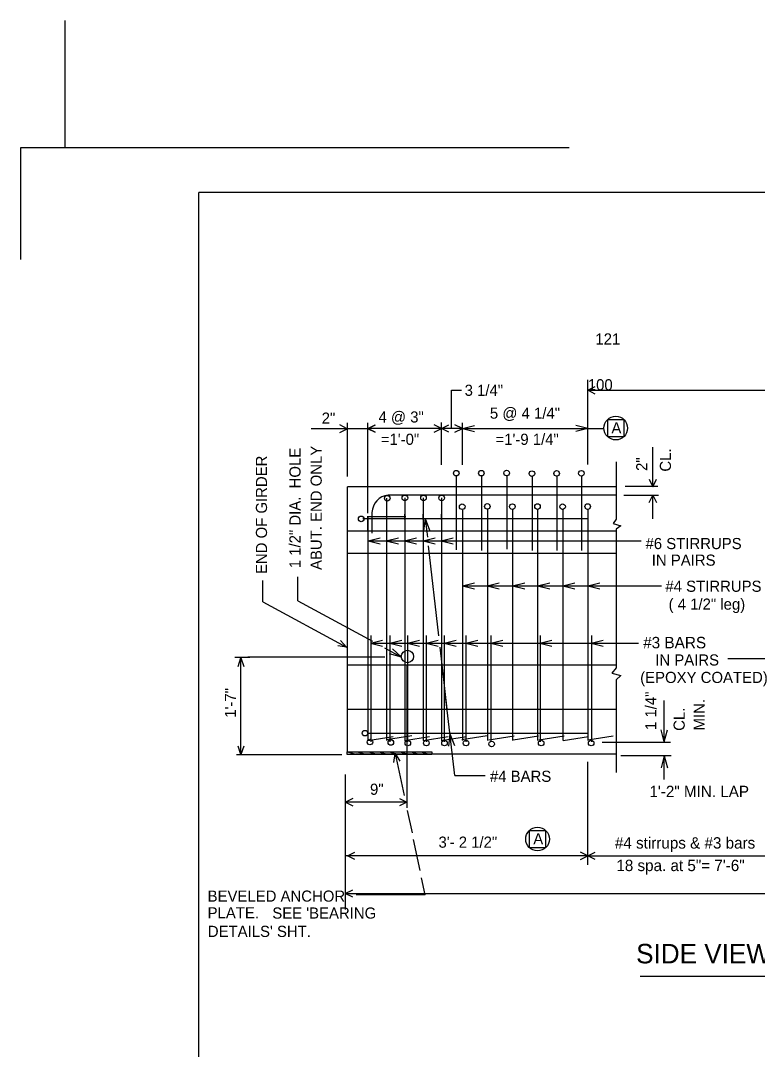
# Model space of a CAD drawing. Extents: x 1005 to 1123, y 2008 to 2074.
# Drawn here: x 1008.66 to 1030.68, y 2043.4 to 2074.18 of the extents above; entities that cross this region are included whole.
import ezdxf

# ---------------------------------------------------------------- set-up
doc = ezdxf.new("R2010")
doc.units = 0
for name, color, linetype in [('Level 1', 7, 'Continuous'), ('Level 2', 7, 'Continuous'), ('Level 5', 7, 'Continuous'), ('Level 6', 7, 'Continuous'), ('Level 60', 7, 'Continuous')]:
    doc.layers.add(name, color=color, linetype=linetype)

msp = doc.modelspace()

# ---------------------------------------------------------------- linework, layer by layer
at = {"layer": 'Level 1'}
for p, q in [((1025.057, 2070.374), (1008.656, 2070.374)), ((1008.656, 2070.374), (1008.656, 2067.034)), ((1013.989, 2013.041), (1013.989, 2069.04)), ((1097.657, 2069.04), (1013.989, 2069.04))]:
    msp.add_line(p, q, dxfattribs=at)
at = {"layer": 'Level 2'}
for p, q in [((1009.989, 2070.374), (1009.989, 2074.178)), ((1025.614, 2060.904), (1025.614, 2063.43)), ((1021.537, 2061.975), (1021.537, 2063.122)), ((1021.537, 2063.122), (1021.839, 2063.122)), ((1025.617, 2063.119), (1052.076, 2063.119)), ((1018.426, 2060.537), (1018.426, 2062.142)), ((1019.039, 2059.444), (1019.039, 2062.142)), ((1021.239, 2060.885), (1021.239, 2062.153)), ((1021.864, 2060.891), (1021.864, 2062.142)), ((1026.698, 2062.239), (1026.198, 2062.239)), ((1026.198, 2062.239), (1026.198, 2061.739)), ((1026.698, 2061.739), (1026.698, 2062.239)), ((1019.039, 2061.97), (1017.341, 2061.97)), ((1021.864, 2061.975), (1019.039, 2061.975)), ((1021.864, 2061.975), (1022.224, 2062.065)), ((1021.864, 2061.975), (1026.089, 2061.975)), ((1021.864, 2061.975), (1022.224, 2061.885)), ((1025.614, 2061.975), (1025.254, 2062.065)), ((1025.614, 2061.975), (1025.254, 2062.065)), ((1025.614, 2061.975), (1025.254, 2061.885)), ((1025.614, 2061.975), (1025.254, 2061.885)), ((1026.198, 2061.739), (1026.698, 2061.739)), ((1026.202, 2061.739), (1026.202, 2061.739)), ((1027.559, 2060.236), (1027.559, 2061.418)), ((1026.466, 2060.978), (1026.466, 2059.266)), ((1021.679, 2060.562), (1021.679, 2058.351)), ((1023.19, 2060.581), (1023.19, 2058.37)), ((1022.434, 2060.543), (1022.434, 2058.332)), ((1023.946, 2060.543), (1023.946, 2058.332)), ((1024.683, 2060.543), (1024.683, 2058.332)), ((1025.42, 2060.543), (1025.42, 2058.332)), ((1026.735, 2060.247), (1027.702, 2060.247)), ((1026.466, 2060.236), (1018.426, 2060.236)), ((1018.426, 2052.307), (1018.426, 2060.236)), ((1026.466, 2059.986), (1019.644, 2059.986)), ((1026.689, 2059.986), (1027.725, 2059.986)), ((1027.559, 2059.277), (1027.559, 2059.986)), ((1019.599, 2059.895), (1019.599, 2053.827)), ((1020.14, 2059.905), (1020.14, 2052.647)), ((1020.696, 2059.905), (1020.696, 2052.647)), ((1021.239, 2059.905), (1021.239, 2052.647)), ((1019.039, 2058.922), (1019.039, 2059.35)), ((1019.039, 2059.347), (1020.169, 2059.347)), ((1019.039, 2059.347), (1019.039, 2052.647)), ((1019.158, 2059.468), (1019.158, 2058.847)), ((1020.14, 2059.25), (1020.14, 2059.411)), ((1020.696, 2059.25), (1020.696, 2059.411)), ((1021.239, 2059.25), (1021.239, 2059.411)), ((1021.864, 2059.541), (1021.864, 2052.647)), ((1022.614, 2059.56), (1022.614, 2052.647)), ((1023.364, 2059.56), (1023.364, 2052.647)), ((1024.114, 2059.57), (1024.114, 2052.647)), ((1024.864, 2059.551), (1024.864, 2052.647)), ((1025.614, 2059.56), (1025.614, 2052.647)), ((1018.885, 2059.28), (1025.614, 2059.28)), ((1020.754, 2059.28), (1020.705, 2058.912)), ((1020.754, 2059.28), (1020.884, 2058.932)), ((1020.754, 2059.28), (1020.817, 2058.725)), ((1026.466, 2059.266), (1026.367, 2059.134)), ((1026.367, 2059.134), (1026.598, 2059.068)), ((1026.598, 2059.068), (1026.466, 2058.97)), ((1026.466, 2058.903), (1018.426, 2058.903)), ((1019.048, 2058.616), (1019.408, 2058.706)), ((1019.59, 2058.616), (1019.95, 2058.706)), ((1020.129, 2058.616), (1020.489, 2058.706)), ((1020.688, 2058.616), (1021.048, 2058.706)), ((1021.229, 2058.616), (1021.589, 2058.706)), ((1026.466, 2058.97), (1026.466, 2054.82)), ((1019.048, 2058.616), (1019.76, 2058.616)), ((1019.048, 2058.616), (1019.408, 2058.526)), ((1019.59, 2058.616), (1019.95, 2058.526)), ((1019.759, 2058.616), (1020.47, 2058.616)), ((1020.129, 2058.616), (1020.489, 2058.526)), ((1020.445, 2058.616), (1027.209, 2058.616)), ((1020.688, 2058.616), (1021.048, 2058.526)), ((1021.156, 2055.779), (1020.847, 2058.47)), ((1021.229, 2058.616), (1021.589, 2058.526)), ((1026.466, 2058.235), (1018.426, 2058.235)), ((1015.896, 2056.792), (1015.896, 2057.432)), ((1021.864, 2057.269), (1022.224, 2057.359)), ((1021.864, 2057.269), (1022.617, 2057.269)), ((1021.864, 2057.269), (1022.224, 2057.179)), ((1022.605, 2057.269), (1022.965, 2057.359)), ((1022.605, 2057.269), (1022.965, 2057.179)), ((1022.617, 2057.269), (1023.366, 2057.269)), ((1023.366, 2057.269), (1023.726, 2057.359)), ((1023.366, 2057.269), (1024.114, 2057.269)), ((1023.366, 2057.269), (1023.726, 2057.179)), ((1024.114, 2057.269), (1024.474, 2057.359)), ((1024.114, 2057.269), (1024.863, 2057.269)), ((1024.114, 2057.269), (1024.474, 2057.179)), ((1024.863, 2057.269), (1025.223, 2057.359)), ((1024.863, 2057.269), (1025.636, 2057.269)), ((1024.863, 2057.269), (1025.223, 2057.179)), ((1025.614, 2057.269), (1025.974, 2057.359)), ((1025.614, 2057.269), (1025.974, 2057.179)), ((1025.636, 2057.269), (1027.819, 2057.269)), ((1015.896, 2056.792), (1018.401, 2055.433)), ((1019.117, 2055.559), (1019.477, 2055.649)), ((1019.123, 2055.784), (1019.123, 2052.602)), ((1019.69, 2055.559), (1020.05, 2055.649)), ((1019.693, 2055.784), (1019.693, 2052.602)), ((1020.22, 2055.559), (1020.58, 2055.649)), ((1020.225, 2055.784), (1020.225, 2052.602)), ((1020.78, 2055.559), (1021.14, 2055.649)), ((1020.782, 2055.784), (1020.782, 2052.602)), ((1021.32, 2055.559), (1021.68, 2055.649)), ((1021.324, 2055.784), (1021.324, 2052.602)), ((1021.963, 2055.559), (1022.323, 2055.649)), ((1021.968, 2055.784), (1021.968, 2052.602)), ((1022.711, 2055.559), (1023.071, 2055.649)), ((1022.716, 2055.784), (1022.716, 2052.602)), ((1024.175, 2055.559), (1024.535, 2055.649)), ((1024.189, 2055.784), (1024.189, 2052.602)), ((1025.711, 2055.559), (1026.071, 2055.649)), ((1025.724, 2055.784), (1025.724, 2052.602)), ((1019.117, 2055.559), (1019.477, 2055.469)), ((1019.123, 2055.559), (1019.884, 2055.559)), ((1019.69, 2055.559), (1020.05, 2055.469)), ((1019.884, 2055.559), (1020.595, 2055.559)), ((1020.22, 2055.559), (1020.58, 2055.469)), ((1020.595, 2055.559), (1022.005, 2055.559)), ((1020.78, 2055.559), (1021.14, 2055.469)), ((1021.408, 2053.583), (1021.195, 2055.44)), ((1021.32, 2055.559), (1021.68, 2055.469)), ((1021.963, 2055.559), (1022.323, 2055.469)), ((1022.005, 2055.559), (1022.754, 2055.559)), ((1022.711, 2055.559), (1023.071, 2055.469)), ((1022.754, 2055.559), (1024.189, 2055.559)), ((1024.175, 2055.559), (1024.535, 2055.469)), ((1024.189, 2055.559), (1025.711, 2055.559)), ((1025.711, 2055.559), (1027.129, 2055.559)), ((1025.711, 2055.559), (1026.071, 2055.469)), ((1031.215, 2055.084), (1029.798, 2055.084)), ((1026.466, 2054.902), (1018.426, 2054.902)), ((1026.466, 2054.82), (1026.334, 2054.656)), ((1026.334, 2054.656), (1026.598, 2054.59)), ((1026.598, 2054.59), (1026.466, 2054.458)), ((1026.466, 2054.458), (1026.466, 2051.69)), ((1019.599, 2053.827), (1019.599, 2052.647)), ((1021.636, 2051.601), (1021.372, 2053.896)), ((1027.901, 2052.603), (1027.901, 2053.841)), ((1026.466, 2053.568), (1018.426, 2053.568)), ((1019.039, 2052.863), (1025.614, 2052.863)), ((1027.901, 2052.603), (1027.811, 2052.963)), ((1027.901, 2052.603), (1027.991, 2052.963)), ((1019.039, 2052.647), (1019.792, 2052.768)), ((1019.599, 2052.674), (1020.352, 2052.795)), ((1020.131, 2052.647), (1020.884, 2052.768)), ((1020.687, 2052.647), (1021.441, 2052.768)), ((1021.23, 2052.647), (1021.983, 2052.768)), ((1021.493, 2052.842), (1021.447, 2052.474)), ((1021.493, 2052.842), (1021.626, 2052.495)), ((1021.85, 2052.674), (1022.603, 2052.795)), ((1022.657, 2052.661), (1023.411, 2052.782)), ((1023.384, 2052.661), (1024.137, 2052.782)), ((1024.151, 2052.661), (1024.904, 2052.782)), ((1024.877, 2052.647), (1025.63, 2052.768)), ((1025.617, 2052.661), (1026.37, 2052.782)), ((1026.04, 2052.595), (1028.087, 2052.595)), ((1018.426, 2052.307), (1018.672, 2052.234)), ((1026.466, 2052.234), (1018.672, 2052.234)), ((1025.614, 2048.921), (1025.614, 2052.008)), ((1026.597, 2052.193), (1028.103, 2052.193)), ((1027.901, 2052.187), (1027.811, 2051.827)), ((1027.901, 2051.479), (1027.901, 2052.187)), ((1027.901, 2052.187), (1027.991, 2051.827)), ((1018.361, 2051.625), (1018.361, 2047.594)), ((1021.636, 2051.601), (1022.542, 2051.601)), ((1024.361, 2049.947), (1023.861, 2049.947)), ((1023.861, 2049.947), (1023.861, 2049.447)), ((1024.361, 2049.447), (1024.361, 2049.947)), ((1025.614, 2049.196), (1018.361, 2049.196)), ((1023.861, 2049.447), (1024.361, 2049.447)), ((1023.866, 2049.447), (1023.866, 2049.447)), ((1025.614, 2049.196), (1033.237, 2049.196)), ((1018.361, 2048.066), (1057.695, 2048.066)), ((1027.181, 2045.596), (1043.723, 2045.596))]:
    msp.add_line(p, q, dxfattribs=at)
for points in [[(1025.836, 2063.008), (1025.614, 2063.119), (1025.836, 2063.23)], [(1019.261, 2061.864), (1019.039, 2061.975), (1019.261, 2062.087)], [(1021.016, 2061.864), (1021.238, 2061.975), (1021.016, 2062.086)], [(1021.461, 2061.864), (1021.239, 2061.975), (1021.461, 2062.086)], [(1021.641, 2061.864), (1021.864, 2061.975), (1021.641, 2062.087)], [(1018.201, 2061.859), (1018.423, 2061.971), (1018.201, 2062.082)], [(1019.263, 2061.859), (1019.041, 2061.971), (1019.263, 2062.082)], [(1021.869, 2061.973), (1021.864, 2061.975), (1021.869, 2061.978)], [(1025.608, 2061.973), (1025.614, 2061.975), (1025.608, 2061.978)], [(1027.448, 2060.458), (1027.559, 2060.236), (1027.67, 2060.458)], [(1027.448, 2059.764), (1027.559, 2059.986), (1027.67, 2059.764)], [(1018.22, 2055.631), (1018.401, 2055.433), (1018.137, 2055.477)], [(1018.648, 2049.081), (1018.426, 2049.192), (1018.648, 2049.303)], [(1025.39, 2049.084), (1025.612, 2049.195), (1025.39, 2049.306)], [(1025.837, 2049.084), (1025.614, 2049.195), (1025.837, 2049.306)], [(1018.584, 2047.955), (1018.361, 2048.066), (1018.584, 2048.178)]]:
    msp.add_lwpolyline(points, dxfattribs=at)
for centre, radius in [((1026.448, 2061.989), 0.354), ((1021.68, 2060.641), 0.0833), ((1022.431, 2060.64), 0.0833), ((1023.186, 2060.644), 0.0833), ((1023.942, 2060.627), 0.0833), ((1024.681, 2060.633), 0.0833), ((1025.421, 2060.637), 0.0833), ((1019.617, 2059.891), 0.0833), ((1020.145, 2059.899), 0.0833), ((1020.701, 2059.899), 0.0833), ((1021.243, 2059.899), 0.0833), ((1021.859, 2059.637), 0.0833), ((1022.609, 2059.646), 0.0833), ((1023.359, 2059.64), 0.0833), ((1024.109, 2059.642), 0.0833), ((1024.859, 2059.638), 0.0833), ((1025.609, 2059.642), 0.0833), ((1018.837, 2059.273), 0.0833), ((1018.953, 2052.863), 0.0833), ((1019.099, 2052.599), 0.0833), ((1019.724, 2052.584), 0.0833), ((1020.232, 2052.569), 0.0833), ((1020.788, 2052.569), 0.0833), ((1021.33, 2052.569), 0.0833), ((1021.974, 2052.569), 0.0833), ((1022.737, 2052.54), 0.0833), ((1024.218, 2052.569), 0.0833), ((1025.715, 2052.569), 0.0833), ((1024.111, 2049.697), 0.354)]:
    msp.add_circle(centre, radius, dxfattribs=at)
msp.add_arc((1019.708, 2059.44), 0.55, 96.657, 177.0425, dxfattribs=at)
at = {"layer": 'Level 5'}
for p, q in [((1016.949, 2056.82), (1016.949, 2057.543)), ((1016.949, 2056.82), (1019.176, 2055.613)), ((1019.531, 2055.421), (1020.047, 2055.141)), ((1020.047, 2055.141), (1019.773, 2055.391)), ((1015.065, 2055.136), (1015.511, 2055.136)), ((1015.245, 2052.225), (1015.245, 2055.116)), ((1019.548, 2055.136), (1015.453, 2055.136)), ((1020.047, 2055.141), (1019.688, 2055.233)), ((1020.204, 2054.903), (1020.204, 2050.634)), ((1018.255, 2052.22), (1015.11, 2052.22)), ((1020.204, 2050.8), (1018.37, 2050.8))]:
    msp.add_line(p, q, dxfattribs=at)
for points in [[(1015.158, 2054.862), (1015.245, 2055.116), (1015.333, 2054.862)], [(1015.158, 2054.862), (1015.245, 2055.116), (1015.333, 2054.862)], [(1015.333, 2052.479), (1015.245, 2052.225), (1015.158, 2052.479)], [(1018.593, 2050.911), (1018.37, 2050.8), (1018.593, 2050.689)], [(1019.981, 2050.911), (1020.204, 2050.8), (1019.981, 2050.689)]]:
    msp.add_lwpolyline(points, dxfattribs=at)
msp.add_circle((1020.221, 2055.158), 0.186, dxfattribs=at)
at = {"layer": 'Level 6'}
for p, q in [((1018.726, 2052.307), (1018.972, 2052.234)), ((1019.057, 2052.307), (1019.304, 2052.234)), ((1019.366, 2052.307), (1019.612, 2052.234)), ((1019.677, 2052.307), (1019.923, 2052.234)), ((1019.85, 2052.253), (1020.119, 2050.997)), ((1019.994, 2052.307), (1020.241, 2052.234)), ((1020.323, 2052.307), (1020.569, 2052.234)), ((1020.623, 2052.307), (1020.869, 2052.234)), ((1020.215, 2050.552), (1020.359, 2049.883)), ((1020.599, 2048.761), (1020.401, 2049.684)), ((1020.756, 2048.032), (1020.646, 2048.542)), ((1020.756, 2048.032), (1018.688, 2048.032))]:
    msp.add_line(p, q, dxfattribs=at)
msp.add_lwpolyline([(1018.424, 2052.307), (1020.946, 2052.307), (1020.946, 2052.231), (1018.424, 2052.231)], close=True, dxfattribs=at)
msp.add_lwpolyline([(1019.817, 2051.987), (1019.85, 2052.253), (1019.989, 2052.023)], dxfattribs=at)

# ---------------------------------------------------------------- texts
at = {"layer": 'Level 2'}
for s, height, p in [('3 1/4"', 0.3333, (1021.931, 2062.953)), ('2"', 0.3333, (1017.657, 2062.12)), ('4 @ 3" ', 0.3333, (1019.356, 2062.155)), ('5 @ 4 1/4"', 0.3333, (1022.686, 2062.27)), ('A', 0.333, (1026.32, 2061.829)), ('=1\'-0"', 0.3333, (1019.424, 2061.488)), ('3\'-9"', 0.00833, (1021.889, 2061.98)), ('=1\'-9 1/4"', 0.3333, (1022.854, 2061.488)), ('#6 STIRRUPS', 0.33333, (1027.339, 2058.369)), ('IN PAIRS', 0.3333, (1027.526, 2057.873)), ('#4 STIRRUPS', 0.33333, (1027.933, 2057.092)), ('( 4 1/2" leg)', 0.33333, (1028.029, 2056.557)), ('#3 BARS', 0.3423, (1027.268, 2055.402)), ('IN PAIRS', 0.3333, (1027.629, 2054.887)), ('(EPOXY COATED)', 0.33333, (1027.179, 2054.365)), ('#4 BARS', 0.3333, (1022.688, 2051.408)), ('1\'-2" MIN. LAP', 0.34001, (1027.456, 2050.951)), ('3\'- 2 1/2"', 0.3333, (1021.15, 2049.438)), ('A', 0.333, (1023.983, 2049.537)), ('#4 stirrups & #3 bars', 0.34001, (1026.423, 2049.412)), ('18 spa. at 5"= 7\'-6"', 0.34001, (1026.467, 2048.738)), (' SIDE VIEW & TYP. SECTION', 0.58333, (1026.841, 2045.978))]:
    msp.add_text(s, height=height, dxfattribs=at).set_placement(p)
for s, height, p in [('CL.', 0.3333, (1028.1, 2060.686)), ('END OF GIRDER', 0.33333, (1016.024, 2057.624)), ('2"', 0.3333, (1027.392, 2060.707)), ('1 1/4"', 0.3333, (1027.663, 2052.959)), ('MIN.', 0.3333, (1029.11, 2052.946)), ('CL.', 0.3333, (1028.511, 2052.934))]:
    msp.add_text(s, height=height, rotation=90, dxfattribs=at).set_placement(p)
at = {"layer": 'Level 5'}
for s, height, p in [('1 1/2" DIA.  HOLE', 0.33333, (1017.026, 2057.797)), ('ABUT. END ONLY', 0.33333, (1017.659, 2057.745)), ('1\'-7"', 0.3333, (1015.096, 2053.326))]:
    msp.add_text(s, height=height, rotation=90, dxfattribs=at).set_placement(p)
msp.add_text('9"', height=0.3333, dxfattribs=at).set_placement((1019.102, 2051.021))
at = {"layer": 'Level 6'}
for s, height, p in [('BEVELED ANCHOR', 0.33333, (1014.247, 2047.824)), ('PLATE.', 0.3333, (1014.247, 2047.324)), ("SEE 'BEARING", 0.33333, (1016.181, 2047.317)), ("DETAILS' SHT.", 0.33333, (1014.254, 2046.769))]:
    msp.add_text(s, height=height, dxfattribs=at).set_placement(p)
at = {"layer": 'Level 60'}
for s, p in [('121', (1025.84, 2064.489)), ('100', (1025.614, 2063.119))]:
    msp.add_text(s, height=0.3333, dxfattribs=at).set_placement(p)

doc.saveas('drawing.dxf')
